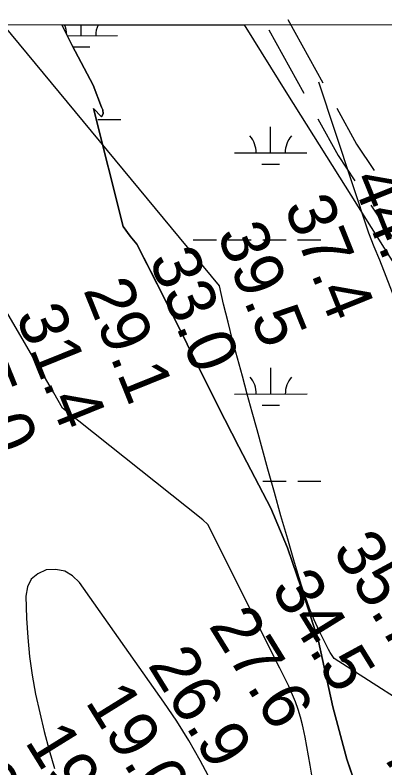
# Model space of a CAD drawing. Extents: x 3279314 to 3317160, y 734079 to 759431.
# Drawn here: x 3288596 to 3289107, y 756619 to 757657 of the extents above; entities that cross this region are included whole.
import ezdxf

# ---------------------------------------------------------------- set-up
doc = ezdxf.new("R2010")
doc.units = 0
for name, color, linetype in [('V-GRID-FRAM', 7, 'Continuous'), ('V-RIVR-RANG', 7, 'Continuous'), ('V-ROAD-CNTR', 7, 'Continuous'), ('V-SITE-VEGE', 7, 'Continuous'), ('V-TOPO-MAJR', 7, 'Continuous'), ('V-TOPO-MINR', 7, 'Continuous'), ('V-TOPO-SHOR', 7, 'Continuous'), ('V-WETL-SWMP', 7, 'Continuous')]:
    doc.layers.add(name, color=color, linetype=linetype)

msp = doc.modelspace()

# ---------------------------------------------------------------- linework, layer by layer
at = {"layer": 'V-GRID-FRAM'}
msp.add_lwpolyline([(3283455.7, 757641.4), (3314923.7, 757657.4), (3314940.9, 739471.9), (3283457, 739455.9), (3283455.7, 757641.4)], dxfattribs=at)
at = {"layer": 'V-ROAD-CNTR'}
for p, q in [((3288973.2, 757651.4), (3289021.5, 757563.8)), ((3288946.9, 757636.9), (3288995.2, 757549.4)), ((3289087.9, 757395.2), (3289143.2, 757311.9))]:
    msp.add_line(p, q, dxfattribs=at)
for points in [[(3289040.8, 757528.8), (3289068.1, 757479.2), (3289092.1, 757443.1)], [(3289014.5, 757514.3), (3289042.5, 757463.6), (3289065.8, 757428.6)]]:
    msp.add_lwpolyline(points, dxfattribs=at)
at = {"layer": 'V-SITE-VEGE'}
for p, q in [((3288660.9, 757644), (3288912.9, 757644.1)), ((3288675.5, 757615.4), (3288660.9, 757644)), ((3288912.9, 757644.1), (3288972.6, 757547.6)), ((3288704.3, 757560.6), (3288675.5, 757615.4)), ((3288715.9, 757530.4), (3288704.3, 757560.6)), ((3288972.6, 757547.6), (3289388, 756887.4)), ((3288745.6, 757365.7), (3288704.6, 757528.4)), ((3288704.6, 757528.4), (3288716, 757517.1)), ((3288717.8, 757526.6), (3288715.9, 757530.4)), ((3288717.9, 757520.9), (3288717.8, 757526.6)), ((3288716, 757517.1), (3288717.9, 757520.9)), ((3288755.2, 757352.5), (3288745.6, 757365.7)), ((3288764.8, 757341.2), (3288755.2, 757352.5)), ((3288807.1, 757258.2), (3288764.8, 757341.2)), ((3288834.1, 757203.4), (3288807.1, 757258.2)), ((3288876.4, 757118.4), (3288834.1, 757203.4)), ((3288905.3, 757061.8), (3288876.4, 757118.4)), ((3288949.6, 756976.8), (3288905.3, 757061.8)), ((3288972.7, 756922.1), (3288949.6, 756976.8)), ((3288998, 756848.3), (3288972.7, 756922.1)), ((3289015.4, 756793.5), (3288998, 756848.3)), ((3289035.1, 756702.7), (3289015.4, 756793.5)), ((3289054.6, 756630.8), (3289035.1, 756702.7)), ((3289097.3, 756506), (3289054.6, 756630.8))]:
    msp.add_line(p, q, dxfattribs=at)
at = {"layer": 'V-TOPO-MAJR'}
for p, q in [((3288649.8, 757136.3), (3288353.2, 757643.9)), ((3288655.8, 757125.6), (3288649.8, 757136.3)), ((3288661.9, 757115), (3288655.8, 757125.6)), ((3288855.7, 756961.1), (3288661.9, 757115)), ((3288862.7, 756954.5), (3288855.7, 756961.1)), ((3288962.2, 756756.4), (3288862.7, 756954.5)), ((3288966.3, 756748.1), (3288962.2, 756756.4)), ((3288970.4, 756739.7), (3288966.3, 756748.1)), ((3288974.3, 756731.3), (3288970.4, 756739.7)), ((3288978.1, 756722.8), (3288974.3, 756731.3)), ((3288979.5, 756719.7), (3288978.1, 756722.8)), ((3288983.6, 756709.6), (3288979.5, 756719.7)), ((3288987.4, 756699.3), (3288983.6, 756709.6)), ((3288990.5, 756688.8), (3288987.4, 756699.3)), ((3288993.2, 756678.2), (3288990.5, 756688.8)), ((3288994.1, 756674), (3288993.2, 756678.2)), ((3288996.9, 756661.2), (3288994.1, 756674)), ((3288999.5, 756648.3), (3288996.9, 756661.2)), ((3289001.8, 756635.4), (3288999.5, 756648.3)), ((3289004, 756622.5), (3289001.8, 756635.4)), ((3289008.5, 756594.8), (3289004, 756622.5))]:
    msp.add_line(p, q, dxfattribs=at)
at = {"layer": 'V-TOPO-MINR'}
for p, q in [((3288878.8, 757283.7), (3288580.7, 757644)), ((3289085.1, 757356.4), (3289016, 757564.6)), ((3289092.2, 757337.5), (3289085.1, 757356.4)), ((3289100.2, 757319), (3289092.2, 757337.5)), ((3289377.7, 756599.3), (3289100.2, 757319)), ((3288884.5, 757258.7), (3288878.8, 757283.7)), ((3288890.5, 757233.7), (3288884.5, 757258.7)), ((3288896.8, 757208.9), (3288890.5, 757233.7)), ((3288903.5, 757184), (3288896.8, 757208.9)), ((3288910.3, 757159.3), (3288903.5, 757184)), ((3288917.1, 757134.5), (3288910.3, 757159.3)), ((3288923.9, 757109.7), (3288917.1, 757134.5)), ((3288930.7, 757085), (3288923.9, 757109.7)), ((3288945.5, 757031), (3288930.7, 757085)), ((3288954.5, 756998.7), (3288945.5, 757031)), ((3288963.6, 756966.5), (3288954.5, 756998.7)), ((3288973, 756934.3), (3288963.6, 756966.5)), ((3288982.5, 756902.2), (3288973, 756934.3)), ((3288992.1, 756870.2), (3288982.5, 756902.2)), ((3288997.3, 756854.2), (3288992.1, 756870.2)), ((3289003.1, 756838.5), (3288997.3, 756854.2)), ((3289009.5, 756823), (3289003.1, 756838.5)), ((3289016.5, 756807.8), (3289009.5, 756823)), ((3289026.9, 756786.5), (3289016.5, 756807.8)), ((3289029.2, 756782.1), (3289026.9, 756786.5)), ((3289031.6, 756777.8), (3289029.2, 756782.1)), ((3289034.2, 756773.6), (3289031.6, 756777.8)), ((3289036.9, 756769.4), (3289034.2, 756773.6)), ((3289214.4, 756656.3), (3289036.9, 756769.4))]:
    msp.add_line(p, q, dxfattribs=at)
msp.add_lwpolyline([(3288866.9, 756601.3), (3288852.1, 756629.1), (3288836.5, 756656.4), (3288819.7, 756683), (3288802.1, 756709.2), (3288685.5, 756874.4), (3288675.8, 756883.7), (3288665, 756890.3), (3288652.7, 756892.6), (3288639.2, 756892.1), (3288627.7, 756886.6), (3288618.7, 756879), (3288613.7, 756868.4), (3288611.2, 756855.8), (3288612.3, 756825.1), (3288613.9, 756798.7), (3288616.4, 756772.5), (3288620.2, 756746.4), (3288624.9, 756720.4), (3288630.7, 756694.5), (3288636.8, 756668.8), (3288643.7, 756643.3), (3288651.1, 756617.9)], dxfattribs=at)
at = {"layer": 'V-TOPO-SHOR'}
for points in [[(3288660.9, 757644), (3288675.5, 757615.4), (3288704.3, 757560.6), (3288715.9, 757530.4), (3288717.8, 757526.6), (3288717.9, 757520.9), (3288716, 757517.1), (3288704.6, 757528.4), (3288745.6, 757365.7)], [(3288745.6, 757365.7), (3288755.2, 757352.5), (3288764.8, 757341.2), (3288784, 757303.5), (3288807.1, 757258.2), (3288834.1, 757203.4), (3288876.4, 757118.4), (3288905.3, 757061.8), (3288949.6, 756976.8), (3288972.7, 756922.1), (3288998, 756848.3), (3289015.4, 756793.5), (3289035.1, 756702.7), (3289054.6, 756630.8), (3289097.3, 756506), (3289124.5, 756415.2), (3289186.3, 756277.4), (3289234.3, 756196.2), (3289316.6, 756090.7)]]:
    msp.add_lwpolyline(points, dxfattribs=at)
at = {"layer": 'V-WETL-SWMP'}
for p, q in [((3288660.9, 757644), (3290571.7, 757645)), ((3288660.9, 757644), (3290571.7, 757645)), ((3288675.5, 757615.4), (3288660.9, 757644)), ((3288675.5, 757615.4), (3288660.9, 757644)), ((3288687.9, 757628.9), (3288687.9, 757644)), ((3288668.6, 757628.9), (3288737.9, 757629)), ((3288704.3, 757560.6), (3288675.5, 757615.4)), ((3288704.3, 757560.6), (3288675.5, 757615.4)), ((3288676.4, 757613.5), (3288699.9, 757613.5)), ((3288715.9, 757530.4), (3288704.3, 757560.6)), ((3288715.9, 757530.4), (3288704.3, 757560.6)), ((3288745.6, 757365.7), (3288704.6, 757528.4)), ((3288704.6, 757528.4), (3288716, 757517.1)), ((3288745.6, 757365.7), (3288704.6, 757528.4)), ((3288704.6, 757528.4), (3288716, 757517.1)), ((3288717.8, 757526.6), (3288715.9, 757530.4)), ((3288717.8, 757526.6), (3288715.9, 757530.4)), ((3288717.9, 757520.9), (3288717.8, 757526.6)), ((3288717.9, 757520.9), (3288717.8, 757526.6)), ((3288710.6, 757513.5), (3288742.6, 757513.5)), ((3288716, 757517.1), (3288717.9, 757520.9)), ((3288716, 757517.1), (3288717.9, 757520.9)), ((3288949.4, 757467.2), (3288949.4, 757503.2)), ((3288899.4, 757467.2), (3288999.4, 757467.2)), ((3288937.4, 757451.8), (3288961.4, 757451.8)), ((3288755.2, 757352.5), (3288745.6, 757365.7)), ((3288755.2, 757352.5), (3288745.6, 757365.7)), ((3288764.8, 757341.2), (3288755.2, 757352.5)), ((3288764.8, 757341.2), (3288755.2, 757352.5)), ((3288842.6, 757347.1), (3288874.6, 757347.1)), ((3288890.6, 757347.1), (3288922.6, 757347.1)), ((3288938.6, 757347.1), (3288970.6, 757347.1)), ((3288986.6, 757347.2), (3289018.6, 757347.2)), ((3288807.1, 757258.2), (3288764.8, 757341.2)), ((3288807.1, 757258.2), (3288764.8, 757341.2)), ((3288834.1, 757203.4), (3288807.1, 757258.2)), ((3288834.1, 757203.4), (3288807.1, 757258.2)), ((3288876.4, 757118.4), (3288834.1, 757203.4)), ((3288876.4, 757118.4), (3288834.1, 757203.4)), ((3288949.6, 757134.5), (3288949.6, 757170.5)), ((3288899.6, 757134.5), (3288999.6, 757134.6)), ((3288905.3, 757061.8), (3288876.4, 757118.4)), ((3288905.3, 757061.8), (3288876.4, 757118.4)), ((3288937.6, 757119.1), (3288961.6, 757119.1)), ((3288949.6, 756976.8), (3288905.3, 757061.8)), ((3288949.6, 756976.8), (3288905.3, 757061.8)), ((3288938.8, 757014.5), (3288970.8, 757014.5)), ((3288986.8, 757014.5), (3289018.8, 757014.5)), ((3288972.7, 756922.1), (3288949.6, 756976.8)), ((3288972.7, 756922.1), (3288949.6, 756976.8)), ((3288998, 756848.3), (3288972.7, 756922.1)), ((3288998, 756848.3), (3288972.7, 756922.1)), ((3289015.4, 756793.5), (3288998, 756848.3)), ((3289015.4, 756793.5), (3288998, 756848.3)), ((3289035.1, 756702.7), (3289015.4, 756793.5)), ((3289035.1, 756702.7), (3289015.4, 756793.5)), ((3289054.6, 756630.8), (3289035.1, 756702.7)), ((3289054.6, 756630.8), (3289035.1, 756702.7)), ((3289097.3, 756506), (3289054.6, 756630.8)), ((3289097.3, 756506), (3289054.6, 756630.8))]:
    msp.add_line(p, q, dxfattribs=at)
for centre, start, end in [((3288632.7, 757629.4), 1.3446, 24.5503), ((3288743.1, 757629.4), 155.508, 180.801), ((3288894.2, 757467.6), 359.2573, 40.801), ((3289004.7, 757467.7), 139.2573, 180.801), ((3288894.3, 757135), 359.2573, 40.801), ((3289004.8, 757135), 139.2573, 180.801)]:
    msp.add_arc(centre, 35.2, start, end, dxfattribs=at)

# ---------------------------------------------------------------- texts
at = {"layer": 'V-RIVR-RANG'}
for s, rotation, p in [('44.4', 291.9383, (3289060, 757430.8)), ('37.4', 291.9383, (3288967.3, 757393.2)), ('39.5', 291.9383, (3288874.7, 757355.6)), ('33.0', 291.9383, (3288780.9, 757320.7)), ('29.1', 291.9383, (3288690.2, 757278.2)), ('31.4', 291.9383, (3288596.7, 757242.8)), ('25.0', 291.9383, (3288502.9, 757207.9)), ('35.7', 301.7483, (3289033.7, 756919)), ('34.5', 301.7483, (3288948.7, 756866.1)), ('27.6', 301.7483, (3288862.9, 756814.9)), ('26.9', 301.7483, (3288778.8, 756760.7)), ('19.0', 301.7483, (3288692.5, 756710.1)), ('19.9', 301.7483, (3288609, 756655)), ('31.7', 313.5383, (3289069.5, 756593.4)), ('28.7', 301.7483, (3288524.2, 756602))]:
    msp.add_text(s, height=67, rotation=rotation, dxfattribs=at).set_placement(p)

doc.saveas('drawing.dxf')
